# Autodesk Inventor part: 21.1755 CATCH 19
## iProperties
Company: MiniTec Framing Systems, LLC
Created: 2007-03
Part Number: 21.1755 CATCH 19
Material: Aluminum-6061
Document SubType Name: Modeling
Designer: Andy Moles
Density: 2.71 g/cm^3
Mass: 103.382 g
Surface Area: 184.017 cm^2
Volume: 38.1483 cm^3
Author: Andy Moles
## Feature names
1. Extrusion1
2. Hole1
3. Mirror1
